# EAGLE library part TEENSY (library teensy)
Teensy 2.0
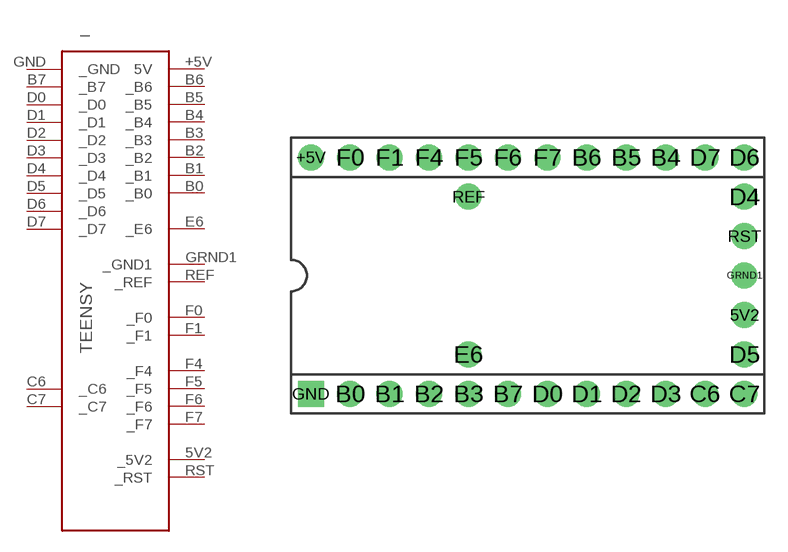
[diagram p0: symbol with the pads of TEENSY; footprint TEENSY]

Designator prefix _

## TEENSY  [TEENSY]
5V2  _5V2
+5V  5V
B0  _B0
B1  _B1
B2  _B2
B3  _B3
B4  _B4
B5  _B5
B6  _B6
B7  _B7
C6  _C6
C7  _C7
D0  _D0
D1  _D1
D2  _D2
D3  _D3
D4  _D4
D5  _D5
D6  _D6
D7  _D7
E6  _E6
F0  _F0
F1  _F1
F4  _F4
F5  _F5
F6  _F6
F7  _F7
GND  _GND
GRND1  _GND1
REF  _REF
RST  _RST

## Footprint TEENSY (pad centres in mm)
drill 0.813 pad 1.676 round: 5V2 13.97,-2.54; +5V -13.97,7.62; B0 -11.43,-7.62; B1 -8.89,-7.62; B2 -6.35,-7.62; B3 -3.81,-7.62; B4 8.89,7.62; B5 6.35,7.62; B6 3.81,7.62; B7 -1.27,-7.62; C6 11.43,-7.62; C7 13.97,-7.62; D0 1.27,-7.62; D1 3.81,-7.62; D2 6.35,-7.62; D3 8.89,-7.62; D4 13.97,5.08; D5 13.97,-5.08; D6 13.97,7.62; D7 11.43,7.62; E6 -3.81,-5.08; F0 -11.43,7.62; F1 -8.89,7.62; F4 -6.35,7.62; F5 -3.81,7.62; F6 -1.27,7.62; F7 1.27,7.62; GRND1 13.97,0; REF -3.81,5.08; RST 13.97,2.54
drill 0.813 pad 1.676 square: GND -13.97,-7.62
